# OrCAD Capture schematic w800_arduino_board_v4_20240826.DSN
size A3; title: Arduino_board; rev: 1.0; note: LINDA
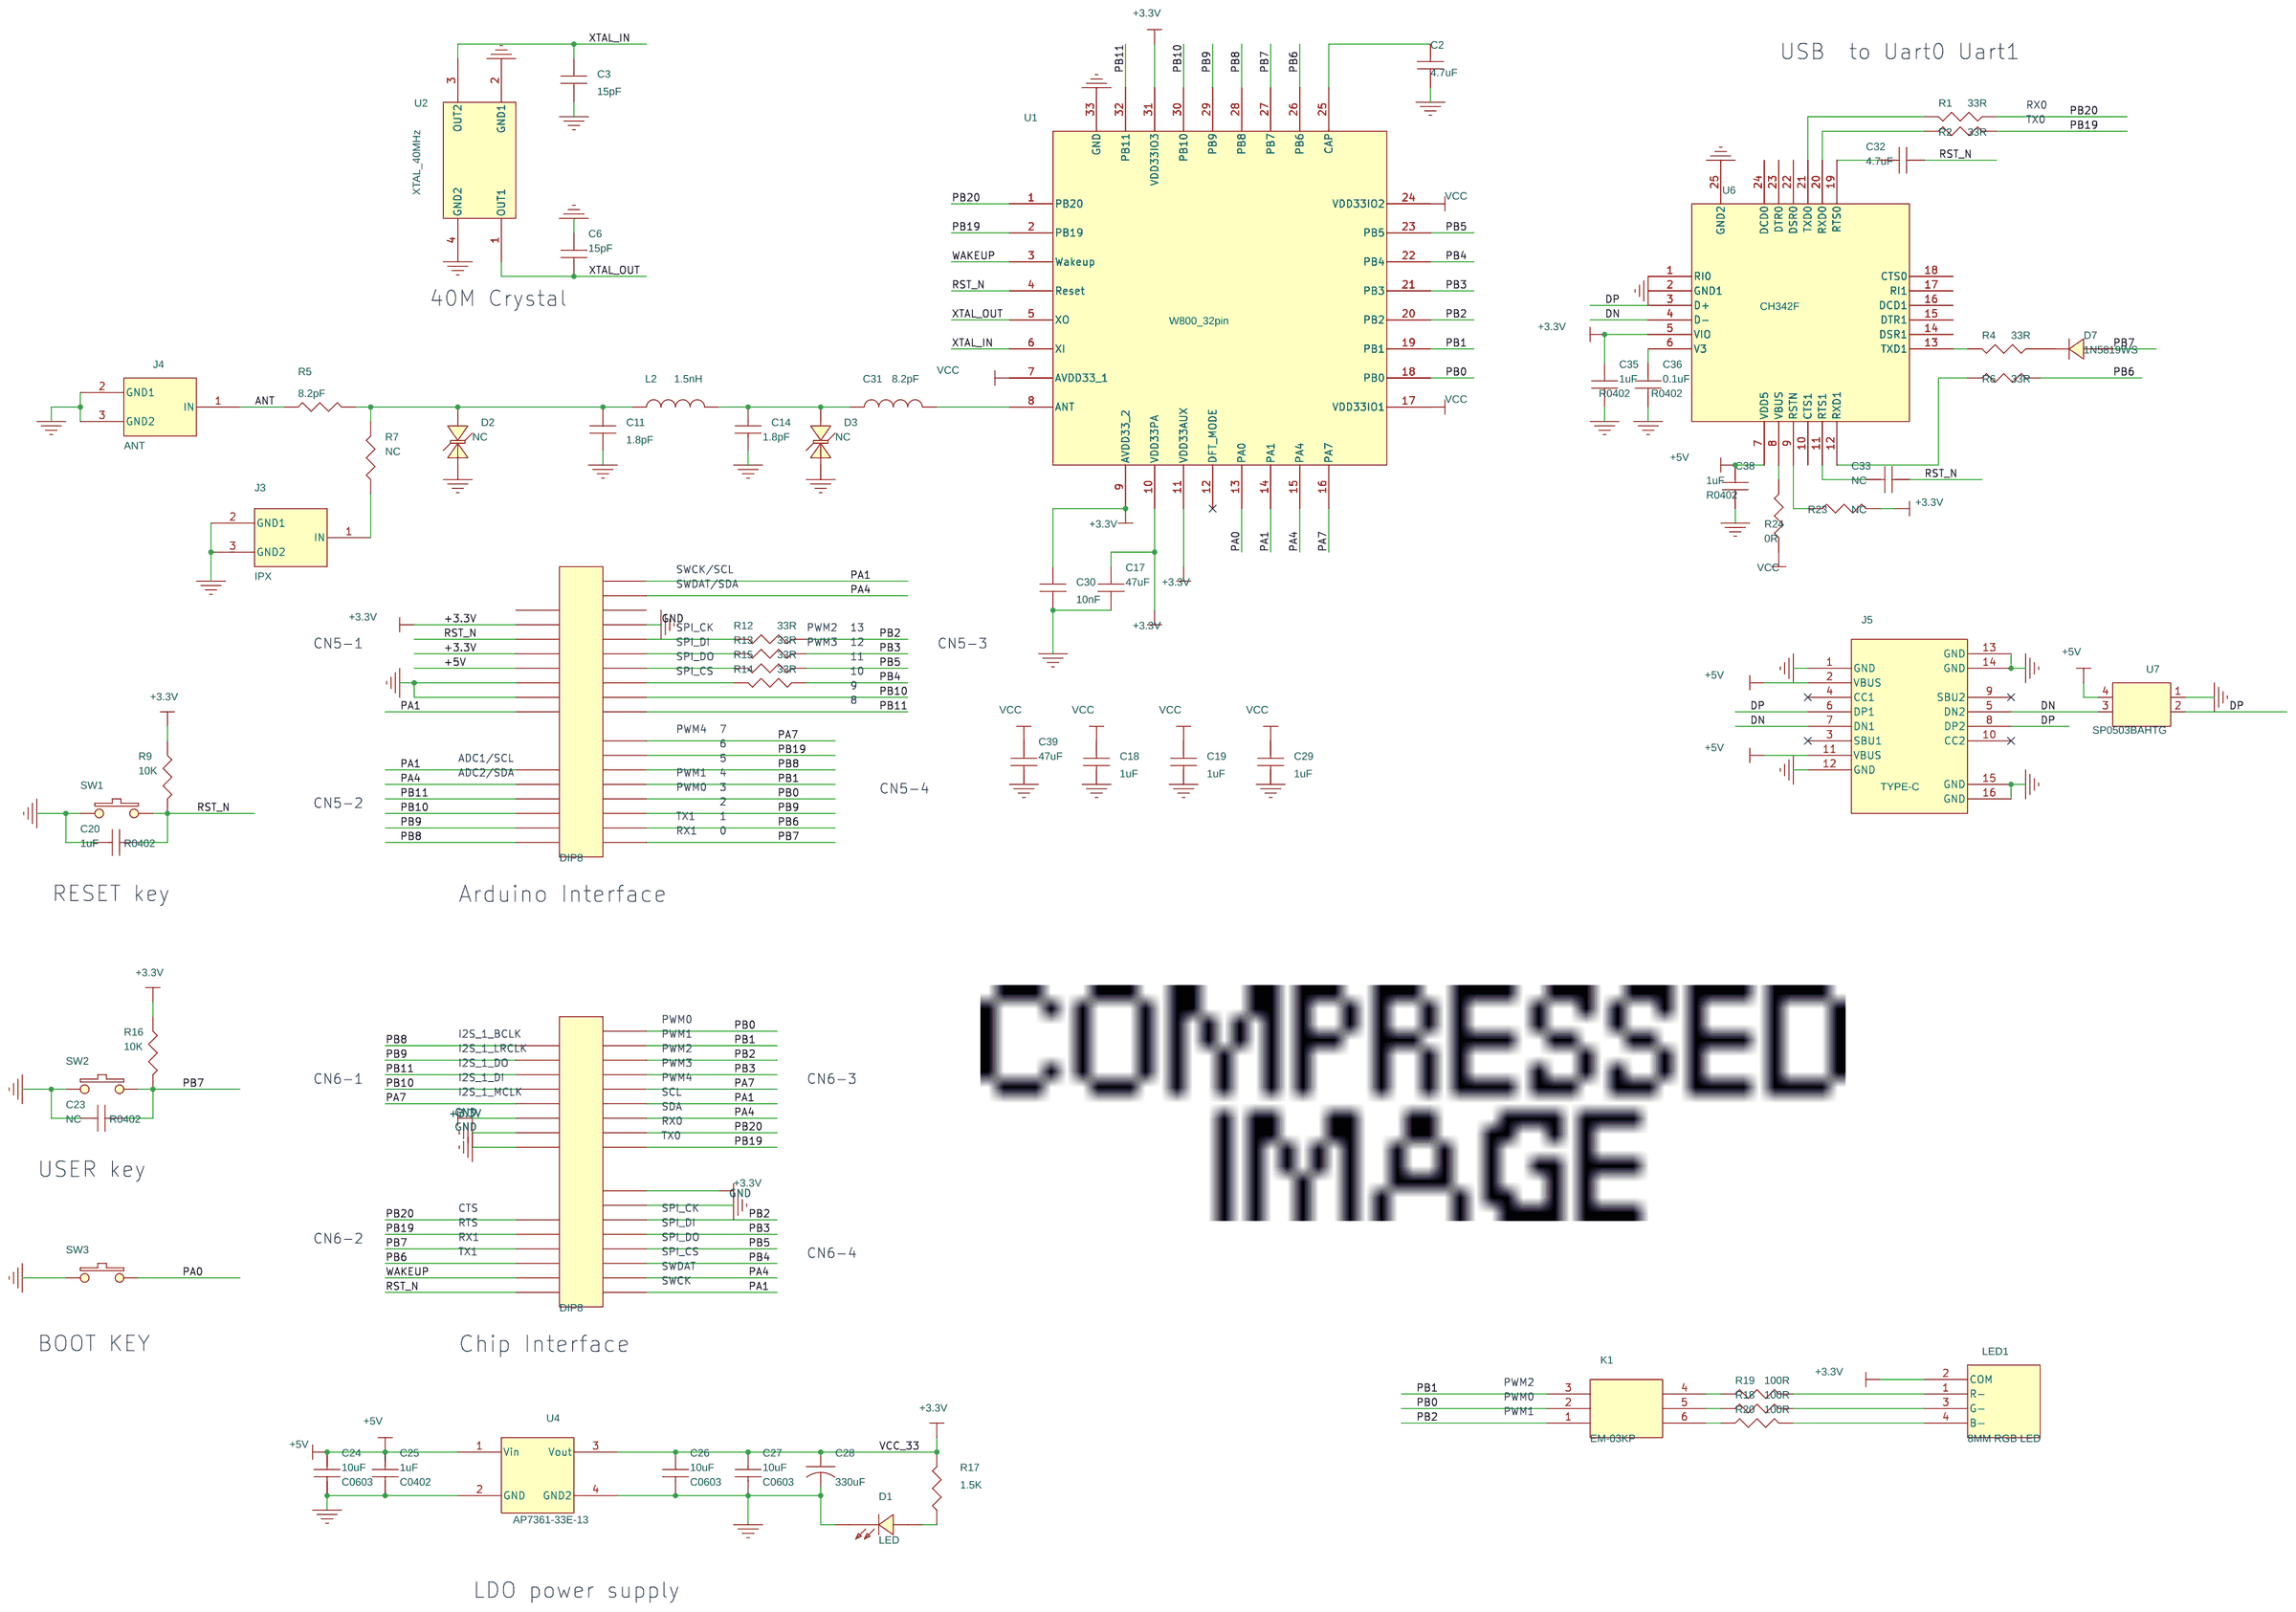
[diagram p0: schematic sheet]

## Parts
C2  4.7uF  [C0402]
C3  15pF  [R0402]
C6  15pF  [R0402]
C11  1.8pF  [C0402]
C14  1.8pF  [C0402]
C17  47uF  [c0805]
C18  1uF  [c0402]
C19  1uF  [c0402]
C20  1uF  [R0402]
C23  NC  [R0402]
C24  10uF  [C0603]
C25  1uF  [C0402]
C26  10uF  [C0603]
C27  10uF  [C0603]
C28  330uF  [cape-6Dx13L]
C29  1uF  [c0402]
C30  10nF  [c0402]
C31  8.2pF  [l0402]
C32  4.7uF  [c0402]
C33  NC  [c0402]
C35  1uF  [R0402]
C36  0.1uF  [R0402]
C38  1uF  [R0402]
C39  47uF  [c0805]
CN5  DIP8  [arduino_hdrm2]
CN6  DIP8  [arduino_hdrmdip]
D1  LED  [LED0603]
D2  NC  [TVS0402]
D3  NC  [TVS0402]
D7  1N5819WS  [SOD-323]
J3  IPX  [TC35]
J4  ANT  [IFA_TI1]
J5  TYPE-C  [type-c]
K1  EM-03KP  [SWITCH3_2]
L2  1.5nH  [l0402]
LED1  8MM RGB LED  [RGB_led]
R1  33R  [R0402]
R2  33R  [R0402]
R4  33R  [R0402]
R5  8.2pF  [R0402]
R6  33R  [R0402]
R7  NC  [R0402]
R9  10K  [R0402]
R12  33R  [R0402]
R13  33R  [R0402]
R14  33R  [R0402]
R15  33R  [R0402]
R16  10K  [R0402]
R17  1.5K  [R0402]
R18  100R  [R0402]
R19  100R  [R0402]
R20  100R  [R0402]
R23  NC  [R0402]
R24  0R  [R0402]
SW1  K2-1107ST-A4SW-06  [sw4]
SW2  K2-1107ST-A4SW-06  [sw4]
SW3  K2-1107ST-A4SW-06  [sw4]
U1  W800_32pin  [w800-qfn32]
U2  XTAL_40MHz  [OSCCC250X320X110]
U4  AP7361-33E-13  [sot-223]
U6  CH342F  [qfn24_4mmx4mm]
U7  SP0503BAHTG  [sot143_2]

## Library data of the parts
C2 C3 C6 C11 C14 C17-C20 C23-C27 C29 C30 C32 C33 C35 C36 C38 C39 = CAP_NP
C28 = C_0: REUSE_ANNOTATE: TRUE; ROOM: PWR
C31 L2 = INDUCTOR
CN5 = CON8_5
CN6 = CON8_9
D1 = LED_0
D2 D3 = TRANZORB_0
D7 = LED_1
J3 J4 = TC35
J5 = TYPE-C_2
K1 = SWITCH_2
LED1 = RGB_0
R1 R2 R4 R6 R12-R15 R17-R20 R23 R24 = R
R5 R7 R9 R16 = R: REUSE_ANNOTATE: TRUE; ROOM: FPGA_BANK3_4_CLK
SW1-SW3 = SW_PUSHBUTTON_0
U1 = W600_10
U2 = OSC44M_0
U4 = AMS117_0
U6 = CP2105_0
U7 = SP0503BAHTG_0

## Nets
+5V: C24.1 C25.1 C38.1 CN5.5 J5.2(VBUS) J5.11(VBUS) R24.2 U4.1(Vin) U6.7(VDD5) U7.4
GND: C2.2 C3.2 C6.1 C11.1 C14.1 C17.2 C18.2 C19.2 C20.1 C23.1 C24.2 C25.2 C26.2 C27.2 C28.2 C29.2 C30.2 C35.2 C36.2 C38.2 C39.2 CN5.6 CN5.7 CN5.29 CN6.7 CN6.8 CN6.21 D1.2 D2.2(CATHODE) D3.2(CATHODE) J3.2(GND1) J3.3(GND2) J4.2(GND1) J4.3(GND2) J5.1(GND) J5.12(GND) J5.13(GND) J5.14(GND) J5.15(GND) J5.16(GND) SW1.2 SW2.2 SW3.2 U1.33(GND) U2.2(GND1) U2.4(GND2) U4.2(GND) U4.4(GND2) U6.2(GND1) U6.25(GND2) U7.1
VCC_33: C17.1 C18.1 C19.1 C26.1 C27.1 C28.1 C29.1 C30.1 C35.1 C39.1 CN5.2 CN5.4 CN6.6 CN6.22 LED1.2(COM) R9.1 R16.1 R17.2 R23.1 U1.7(AVDD33_1) U1.9(AVDD33_2) U1.10(VDD33PA) U1.11(VDD33AUX) U1.17(VDD33IO1) U1.24(VDD33IO2) U1.31(VDD33IO3) U4.3(Vout) U6.5(VIO)
ANT: J4.1(IN) R5.1
DN: J5.5(DN2) J5.7(DN1) U6.4(D-) U7.3
DP: J5.6(DP1) J5.8(DP2) U6.3(D+) U7.2
PA0: SW3.1 U1.13(PA0)
PA1: CN5.8 CN5.9 CN5.32 CN6.15 CN6.27 U1.14(PA1)
PA4: CN5.10 CN5.31 CN6.16 CN6.26 U1.15(PA4)
PA7: CN5.22 CN6.5 CN6.28 U1.16(PA7)
PB0: CN5.18 CN6.32 K1.2 U1.18(PB0)
PB1: CN5.19 CN6.31 K1.3 U1.19(PB1)
PB2: CN6.20 CN6.30 K1.1 R12.1 U1.20(PB2)
PB3: CN6.19 CN6.29 R13.1 U1.21(PB3)
PB4: CN6.17 R14.1 U1.22(PB4)
PB5: CN6.18 R15.1 U1.23(PB5)
PB6: CN5.16 CN6.12 R6.2 U1.26(PB6)
PB7: C23.2 CN5.15 CN6.11 D7.2(ANODE) R16.2 SW2.1 U1.27(PB7)
PB8: CN5.14 CN5.20 CN6.1 U1.28(PB8)
PB9: CN5.13 CN5.17 CN6.2 U1.29(PB9)
PB10: CN5.12 CN5.24 CN6.4 U1.30(PB10)
PB11: CN5.11 CN5.23 CN6.3 U1.32(PB11)
PB19: CN5.21 CN6.10 CN6.24 R2.2 U1.2(PB19)
PB20: CN6.9 CN6.25 R1.1 U1.1(PB20)
RST_N: C20.2 C32.1 C33.1 CN5.3 CN6.14 R9.2 SW1.1 U1.4(Reset)
WAKEUP: CN6.13 U1.3(Wakeup)
XTAL_IN: C3.1 U1.6(XI) U2.3(OUT2)
XTAL_OUT: C6.2 U1.5(XO) U2.1(OUT1)
N16680375: D1.1 R17.1
N16684582: R4.2 U6.13(TXD1)
N16684586: R6.1 U6.12(RXD1)
N16727459: K1.5 R18.1
N16727471: LED1.3(G-) R18.2
N16730113: K1.4 R19.1
N16730133: K1.6 R20.1
N16730206: LED1.4(B-) R20.2
N16730210: LED1.1(R-) R19.2
N16735482: C33.2 U6.11(RTS1)
N16736464: C32.2 U6.19(RTS0)
N16746225: C11.2 D2.1(ANODE) L2.2 R5.2 R7.2
N16746337: C2.1 U1.25(CAP)
N16746437: C14.2 C31.2 D3.1(ANODE) L2.1
N16750371: J3.1(IN) R7.1
N16770024: CN5.28 R12.2
N16770030: CN5.27 R13.2
N16770036: CN5.26 R15.2
N16770042: CN5.25 R14.2
N16796539: C31.1 U1.8(ANT)
N16801010: R1.2 U6.21(TXD0)
N16801016: R2.1 U6.20(RXD0)
N16801188: C36.1 U6.6(V3)
N16801254: R23.2 U6.9(RSTN)
N16806862: D7.1(CATHODE) R4.1
N16808784: R24.1 U6.8(VBUS)

Not connected (* = marked no-connect by the designer): CN5 1 30; J5 3(SBU1)* 4(CC1)* 9(SBU2)* 10(CC2)*; U1 12(DFT_MODE)*; U6 1(RI0) 10(CTS1) 14(DSR1) 15(DTR1) 16(DCD1) 17(RI1) 18(CTS0) 22(DSR0) 23(DTR0) 24(DCD0)

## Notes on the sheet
- USB  to Uart0 Uart1
- RX0
- TX0
- 40M Crystal
- SWCK/SCL
- SWDAT/SDA
- SPI_CK
- PWM2
- 13
- CN5-1
- SPI_DI
- PWM3
- 12
- CN5-3
- SPI_DO
- 11
- SPI_CS
- 10
- 9
- 8
- PWM4
- 7
- 6
- ADC1/SCL
- 5
- ADC2/SDA
- PWM1
- 4
- PWM0
- 3
- CN5-4
- CN5-2
- TX1
- 1
- 2
- RX1
- 0
- RESET key
- Arduino Interface
- PWM0
- I2S_1_BCLK
- PWM1
- I2S_1_LRCLK
- PWM2
- I2S_1_DO
- PWM3
- CN6-1
- I2S_1_DI
- PWM4
- CN6-3
- I2S_1_MCLK
- SCL
- SDA
- RX0
- TX0
- USER key
- CTS
- SPI_CK
- RTS
- SPI_DI
- CN6-2
- RX1
- SPI_DO
- TX1
- SPI_CS
- CN6-4
- SWDAT
- SWCK
- BOOT KEY
- Chip Interface
- PWM0
- PWM2
- PWM1
- LDO power supply
